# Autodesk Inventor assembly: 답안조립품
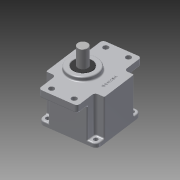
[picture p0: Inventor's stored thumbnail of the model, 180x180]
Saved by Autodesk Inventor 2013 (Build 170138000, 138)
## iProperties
Created: 2015-07
Part Number: 답안조립품
Document SubType Name: Assembly
Designer: user
Author: user
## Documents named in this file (12)
- C:\Users\user\Desktop\450734V1016\답안조립품.iam
- C:\Users\user\Desktop\450734V1016\메인축.ipt
- C:\Users\user\Desktop\450734V1016\베어링 608.ipt
- 베어링 608.ipt
- C:\Users\user\Desktop\450734V1016\서브축.ipt
- C:\Users\user\Desktop\450734V1016\베어링 6003.ipt
- 베어링 6003.ipt
- C:\Users\user\Desktop\450734V1016\본체.ipt
- C:\Users\user\Desktop\450734V1016\커버.ipt
- C:\Users\user\Desktop\450734V1016\오일실 17x32x8.ipt
- C:\Users\user\Desktop\450734V1016\오일실 8x22x7.ipt
- C:\Users\user\Desktop\450734V1016\M4x0.5x16.ipt
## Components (4 placed, 1 different names)
1. M4x0.5x12:1
2. M4x0.5x12:2
3. M4x0.5x12:3
4. M4x0.5x12:4
